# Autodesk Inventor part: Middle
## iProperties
Created: 2010-02
Part Number: Middle
Document SubType Name: Modeling
Designer: jgehrig
Density: 1 g/cm^3
Author: jgehrig
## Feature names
1. Extrusion1
2. Extrusion2
3. Extrusion3
